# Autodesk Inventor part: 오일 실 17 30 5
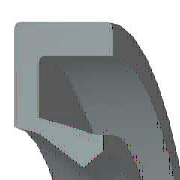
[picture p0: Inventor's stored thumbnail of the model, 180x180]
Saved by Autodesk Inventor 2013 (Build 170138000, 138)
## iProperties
IsCustomPart: 1
Created: 2012-02
Part Number: 오일 실 17 30 5
Material: 고무
Description: 오일 실 - 비스프링, 조립 GA
Document SubType Name: Modeling
Standard: JIS B 2402
Designer: mduedu
Standards Organization: JIS
Language: ko-KR
Size Designation: 17 30 5 A
Categories: <MemberInstance><Categories><Category DisplayName="샤프트 부품" InternalName="7f7aeb1f-a693-4053-b835-cee3144e0d98" Mnemonic="SHFT"><Category DisplayName="실링" Intern
Density: 0.93 g/cm^3
Mass: 1.39335 g
Surface Area: 19.422 cm^2
Volume: 1.49822 cm^3
Author: mduedu
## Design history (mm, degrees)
body "Solid1"
revolve "회전1" stored, may be unused: angle "d27" = 360 deg
fillet "모깎기1" dims "d28" = 0.25 (= 0.05 x b)
sketch "스케치2"
  geometry: L1 (10.636, -3.75)-(11.286, -5); L2 (9.769, -3.438)-(10.636, -3.75); L3 (8.5, -1.375)-(9.769, -3.438); L4 (9.5, -0.75)-(8.5, -1.375); L5 (12.4, -4.375)-(9.5, -0.75); L6 (12.4, -0.25)-(12.4, -4.375); L7 (13.7, -0.25)-(12.4, -0.25); L8 (13.7, 0)-(13.7, -0.25); L9 (15, 0)-(13.7, 0); L10 (15, -5)-(15, 0); L11 (11.286, -5)-(15, -5); L12 (0, -9.6)-(0, 1.6) reference; L13 (28, 0)-(14, 0) reference
  constraints: 22 end point, 3 horizontal, 3 vertical
  dimensions: "d2" = 5 distance of L10.start L9.start (= b); "d4" = 1.3 distance of L9.start L8.start (= 0.1 x dd - 0.1 x Diam); "d6" = 0.25 distance of L8.start L7.start (= 0.05 x b); "d8" = 1 horizontal distance of L4.start L3.start (= 0.0769231 x dd - 0.0769231 x Diam); "d10" = 0.625 vertical distance of L5.start L10.start (= 0.125 x b); "d12" = 1.3 distance of L7.start L6.start (= 0.1 x dd - 0.1 x Diam); "d14" = 0.5 vertical distance of L4.start L6.start (= 0.1 x b); "d16" = 3.71429 distance of L1.end L10.start (= 0.285714 x dd - 0.285714 x Diam); "d18" = 0.65 horizontal distance of L1.start L1.end (= 0.05 x dd - 0.05 x Diam); "d20" = 0.625 vertical distance of L4.start L3.start (= 0.125 x b); "d22" = 1.25 vertical distance of L1.start L1.end (= 0.25 x b); "d24" = 0.86667 horizontal distance of L2.start L1.start (= 0.0666667 x dd - 0.0666667 x Diam); "d26" = 0.3125 vertical distance of L2.start L1.start (= 0.0625 x b); "d29" = 0 distance between parallel lines of L13 L9; "d30" = 8.5 distance from line of L3.start L12 (= 0.5 x Diam); "d31" = 15 distance between parallel lines of L12 L10 (= 0.5 x dd)
other parameters: "Diam" = 17 [user parameter; used in 7 equation terms], "b" = 5 [user parameter; used in 8 equation terms], "d1" = 8 (derived), "d3" = 2 (derived), "d5" = 0.4 (derived), "d7" = 1.53846 (derived), "d9" = 1 (derived), "d11" = 2 (derived), "d13" = 0.8 (derived), "d15" = 5.71429 (derived), "d17" = 1 (derived), "d19" = 1 (derived), "d21" = 2 (derived), "d23" = 1.33333 (derived), "d25" = 0.5 (derived), "d32" = 0
